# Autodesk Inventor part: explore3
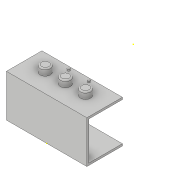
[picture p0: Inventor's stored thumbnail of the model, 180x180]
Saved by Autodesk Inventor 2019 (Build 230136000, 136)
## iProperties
Created: 2020-02
Part Number: explore3
Material: Generic
Document SubType Name: Modeling
Designer: Naveen G
Density: 1 g/cm^3
Appearance: Default
Author: Naveen G
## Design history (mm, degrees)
sketch "Sketch1"
  geometry: L1 (0, 0)-(40, 0); L2 (40, 0)-(40, -40); L3 (40, -40)-(0, -40); L4 (0, -40)-(0, 0)
  constraints: 8 end point, 2 parallel, 1 horizontal, 1 perpendicular
  dimensions: "d0" = 40 distance of L2.end L3.end; "d1" = 40 distance of L1.end L2.end
extrude "Extrusion1" new body sketch "Sketch1" distance "d2" = 20; taper "d3" = 0 deg
sketch "Sketch2"
  geometry: L1 (0, 0)-(0, -40) reference; L2 (0, -40)-(-40, -40); L3 (-40, -40)-(-40, -60); L4 (-40, -60)-(0, -60); L5 (0, -60)-(0, -40); L6 (-40, -60)-(-60, -60); L7 (-60, -60)-(-60, 0); L8 (-60, 0)-(-40, 0); L9 (-40, 0)-(-40, -60)
  constraints: 16 end point, 4 parallel, 2 horizontal, 2 perpendicular
  dimensions: "d4" = 40 distance of L4.end L3.end; "d5" = 20 distance of L3.end L2.end; "d6" = 20 distance of L7.end L8.end; "d7" = 60 distance of L6.end L7.end
extrude "Extrusion2" join sketch "Sketch2" distance "d8" = 40; taper "d9" = 0 deg
sketch "Sketch3"
  geometry: L1 (0, 0)-(-60, 0) reference; L2 (-60, 0)-(-40, 0); L3 (-40, 0)-(-40, 20); L4 (-40, 20)-(-60, 20); L5 (-60, 20)-(-60, 0); L6 (-40, 0)-(-20, 0); L7 (-20, 0)-(-20, 20); L8 (-20, 20)-(-40, 20); L9 (-40, 20)-(-40, 0)
  constraints: 16 end point, 4 parallel, 2 horizontal, 2 perpendicular
  dimensions: "d10" = 20 distance of L4.end L3.end; "d11" = 20 distance of L3.end L2.end; "d12" = 20 distance of L8.end L7.end; "d13" = 20 distance of L7.end L6.end
extrude "Extrusion3" join sketch "Sketch3" distance "d14" = 40; taper "d15" = 0 deg
sketch "Sketch4"
  geometry: L1 (-40, 0)-(-20, 0); L2 (-20, 0)-(-20, 20); L3 (-20, 20)-(-40, 20); L4 (-40, 20)-(-40, 0); 1 further point
  constraints: 8 end point, 2 parallel, 1 horizontal, 1 perpendicular
  dimensions: "d16" = 20 distance of L3.end L2.end; "d17" = 20 distance of L2.end L1.end
extrude "Extrusion4" join sketch "Sketch4" distance "d18" = 20; taper "d19" = 0 deg
sketch "Sketch5"
  geometry: L1 (-20, -20)-(-20, 0) reference; L2 (-20, 0)-(-30, 0); L3 (-30, 0)-(-30, -10); C1 r 7.5 at (-30, -10); 1 further point
  constraints: 4 end point, 1 centre point, 1 coincident, 1 horizontal, 1 perpendicular
  dimensions: "d20" = 10 distance of L1.end L2.end; "d21" = 10 distance of L2.end L3.end; "d22" = 15 diameter of C1
extrude "Extrusion5" join sketch "Sketch5" distance "d23" = 20; taper "d24" = 0 deg
sketch "Sketch6"
  geometry: L1 (-20, 20)-(-20, 0) reference; L2 (-20, 20)-(0, 20); L3 (0, 20)-(0, 0); L4 (0, 0)-(-20, 0); L5 (-20, 0)-(-20, 20)
  constraints: 8 end point, 2 parallel, 1 horizontal, 1 perpendicular
  dimensions: "d25" = 20 distance of L3.end L4.end (derived); "d26" = 20 distance of L2.end L3.end (derived)
extrude "Extrusion6" join sketch "Sketch6" distance "d27" = 40; taper "d28" = 0 deg
sketch "Sketch7"
  geometry: C1 r 1.5 at (0, 0); 1 further point
  constraints: 1 centre point
  dimensions: "d29" = 3 diameter of C1
extrude "Extrusion7" join sketch "Sketch7" distance "d30" = 5; taper "d31" = 0 deg
sketch "Sketch8"
  geometry: L1 (-0.857, 1.041)-(0.931, 1.041); L2 (0.931, 1.041)-(0.931, -1.035); L3 (0.931, -1.035)-(-0.857, -1.035); L4 (-0.857, -1.035)-(-0.857, 1.041); 1 further point
  constraints: 8 end point, 2 parallel, 1 horizontal, 1 perpendicular
extrude "Extrusion8" join sketch "Sketch8" distance "d32" = 2; taper "d33" = 0 deg
sketch "Sketch9"
  geometry: L1 (2.357, 0)-(-0.643, 0) reference; L2 (-0.643, 0)-(0.857, 0); L3 (0.857, 0)-(0.857, 1.5); C1 r 1.5 at (0.857, 1.5); 1 further point
  constraints: 4 end point, 1 centre point, 1 coincident, 1 midpoint, 1 perpendicular
  dimensions: "d34" = 1.5 distance of L1.end L2.end (derived); "d35" = 1.5 distance of L2.end L3.end; "d36" = 3 diameter of C1
extrude "Extrusion9" join sketch "Sketch9" stored distance "d37" = 50; taper "d38" = 0 deg
sketch "Sketch10"
  geometry: L1 (-40, 40)-(0, 40) reference; L2 (0, 40)-(-40, 40); L3 (-40, 40)-(-40, 41); L4 (-40, 41)-(0, 41); L5 (0, 41)-(0, 40); 1 further point
  constraints: 8 end point, 2 parallel, 1 horizontal, 1 perpendicular
  dimensions: "d39" = 40 distance of L3.end L4.end; "d40" = 1 distance of L2.end L3.end
extrude "Extrusion10" cut sketch "Sketch10" distance "d41" = 20; taper "d42" = 0 deg
sketch "Sketch11"
  geometry: L1 (0, 76.363)-(-60, 76.363); L2 (-60, 76.363)-(-60, 126.363); L3 (-60, 126.363)-(0, 126.363); L4 (0, 126.363)-(0, 76.363); L5 (0, 76.363)-(60, 76.363); L6 (60, 76.363)-(60, 126.363); L7 (60, 126.363)-(0, 126.363); L8 (0, 126.363)-(0, 76.363); L9 (-60, 76.363)-(60, 76.363); L10 (60, 76.363)-(60, 126.363); L11 (60, 126.363)-(-60, 126.363); L12 (-60, 126.363)-(-60, 76.363); 1 further point
  constraints: 24 end point, 4 parallel, 4 perpendicular, 3 horizontal
  dimensions: "d43" = 60 distance of L1.start L1.end; "d44" = 50 distance of L1.end L2.end; "d45" = 60 distance of L2.end L3.end; "d46" = 60 distance of L7.end L6.end
extrude "Extrusion11" join sketch "Sketch11" distance "d47" = 3; taper "d48" = 0 deg
sketch "Sketch12"
  geometry: L1 (-60, 76.363)-(-60, 126.363) reference; L2 (-60, 126.363)-(60, 126.363); L3 (60, 126.363)-(60, 129.363); L4 (60, 129.363)-(-60, 129.363); L5 (-60, 129.363)-(-60, 126.363); 1 further point
  constraints: 8 end point, 2 parallel, 1 horizontal, 1 perpendicular
  dimensions: "d49" = 120 distance of L4.end L3.end; "d50" = 3 distance of L3.end L2.end
extrude "Extrusion12" join sketch "Sketch12" distance "d51" = 60; taper "d52" = 0 deg
sketch "Sketch13"
  geometry: L1 (60, -76.363)-(-60, -76.363) reference; L2 (-60, -129.363)-(60, -129.363) reference; L3 (-60, -76.363)-(60, -76.363); L4 (60, -76.363)-(60, -129.363); L5 (60, -129.363)-(-60, -129.363); L6 (-60, -129.363)-(-60, -76.363); 1 further point
  constraints: 8 end point, 2 parallel, 1 horizontal, 1 perpendicular
extrude "Extrusion13" join sketch "Sketch13" distance "d53" = 3; taper "d54" = 0 deg
sketch "Sketch14"
  geometry: L1 (-60, -129.363)-(-60, -76.363) reference; L2 (-60, -76.363)-(-60, -101.363); L3 (-60, -101.363)-(60, -101.363); L4 (60, -101.363)-(30, -101.363); L5 (30, -101.363)-(0, -101.363); L6 (0, -101.363)-(-30, -101.363); C1 r 7.5 at (-30, -101.363); C2 r 7.5 at (0, -101.363); C3 r 7.5 at (30, -101.363); 1 further point
  constraints: 10 end point, 3 centre point, 3 coincident, 3 point on line, 1 midpoint, 1 perpendicular
  dimensions: "d55" = 25 distance of L1.end L2.end; "d56" = 120 distance of L2.end L3.end; "d57" = 30 distance of L3.end L4.end; "d58" = 30 distance of L4.end L5.end; "d59" = 30 distance of L5.end L6.end; "d60" = 15 diameter of C1; "d61" = 15 diameter of C2; "d62" = 15 diameter of C3
extrude "Extrusion14" join sketch "Sketch14" distance "d63" = 10; taper "d64" = 0 deg
fillet "Fillet1" dims "d65" = 2
sketch "Sketch15"
  geometry: L1 (60, -76.363)-(-60, -76.363) reference; L2 (0, -76.363)-(0, -81.363); L3 (0, -81.363)-(15, -81.363); L4 (15, -81.363)-(-15, -81.363); C1 r 2 at (-15, -81.363); C2 r 2 at (15, -81.363); 1 further point
  constraints: 6 end point, 2 centre point, 2 coincident, 1 midpoint, 1 perpendicular, 1 point on line, 1 vertical
  dimensions: "d66" = 5 distance of L2.start L2.end; "d67" = 15 distance of L2.end L3.end; "d68" = 30 distance of L3.end L4.end; "d69" = 4 diameter of C1; "d70" = 4 diameter of C2
extrude "Extrusion15" join sketch "Sketch15" distance "d71" = 4; taper "d72" = 0 deg
fillet "Fillet2" dims "d73" = 2
sketch "Sketch16"
  geometry: 1 further point
sketch "Sketch17"
  geometry: 1 further point
sketch "Sketch18"
  geometry: L1 (-60, -60)-(-60, 20) reference; L2 (-60, -60)-(0, -60); L3 (0, -60)-(0, 38.439); L4 (0, 38.439)-(-60, 38.439); L5 (-60, 38.439)-(-60, -60); 1 further point
  constraints: 8 end point, 2 parallel, 1 horizontal, 1 perpendicular
extrude "Extrusion16" cut sketch "Sketch18" extent not by distance; stored distance "d74" = 0; taper "d75" = 0 deg
body "Solid1"
